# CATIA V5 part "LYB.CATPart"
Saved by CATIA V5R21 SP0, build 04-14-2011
Part number: LYB.SLDPRT
Bounding box of the stored display mesh (mm): x 1.55 to 5.05, y 3.678 to 6.478, z -1.805 to -0.004
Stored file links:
  C:\Users\user\Desktop\CATIA文件\0-最新文件(2025.3月之前的慎用)\LYB\LYB.CATPart
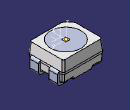
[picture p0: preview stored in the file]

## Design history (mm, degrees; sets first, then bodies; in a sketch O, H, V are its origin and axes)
AxisSystem1: origin (3.2993, 5.0728, -0.0046), X (0, -1, 0), Y (1, 0, 0), Z (0, 0, 1)
Set1
  DatumSurface1 to DatumSurface120
  Line1: stored without definition
  Circle1: stored without definition
  Line2: stored without definition
  Circle2: stored without definition
  Line3 to Line38: stored without definition
  Circle3: stored without definition
  Line39: stored without definition
  Circle4: stored without definition
  Line40 to Line43: stored without definition
  Circle5: stored without definition
  Circle6: stored without definition
  Line44 to Line46: stored without definition
  Circle7: stored without definition
  Line47: stored without definition
  Circle8: stored without definition
  Line48 to Line50: stored without definition
  Circle9 to Circle11: stored without definition
  Line51: stored without definition
  Circle12: stored without definition
  Line52: stored without definition
  Circle13 to Circle15: stored without definition
  Line53: stored without definition
  Circle16: stored without definition
  Line54: stored without definition
  Circle17 to Circle19: stored without definition
  Line55: stored without definition
  Circle20: stored without definition
  Line56: stored without definition
  Circle21 to Circle23: stored without definition
  Line57: stored without definition
  Circle24: stored without definition
  Line58: stored without definition
  Circle25: stored without definition
  Circle26: stored without definition
  Line59 to Line62: stored without definition
  Circle27: stored without definition
  Circle28: stored without definition
  Line63 to Line66: stored without definition
  Circle29: stored without definition
  Circle30: stored without definition
  Line67: stored without definition
  Circle31: stored without definition
  Line68: stored without definition
  Circle32: stored without definition
  Line69 to Line72: stored without definition
  Circle33: stored without definition
  Line73: stored without definition
  Circle34: stored without definition
  Circle35: stored without definition
  Line74: stored without definition
  Circle36: stored without definition
  Line75 to Line78: stored without definition
  Circle37: stored without definition
  Line79: stored without definition
  Circle38: stored without definition
  Line80 to Line82: stored without definition
  Circle39: stored without definition
  Line83: stored without definition
  Circle40: stored without definition
  Line84 to Line86: stored without definition
  Circle41: stored without definition
  Line87: stored without definition
  Circle42: stored without definition
  Line88 to Line90: stored without definition
  Circle43: stored without definition
  Line91: stored without definition
  Circle44: stored without definition
  Circle45: stored without definition
  Line92: stored without definition
  Circle46: stored without definition
  Line93 to Line95: stored without definition
  Circle47: stored without definition
  Line96: stored without definition
  Circle48: stored without definition
  Circle49: stored without definition
  Line97: stored without definition
  Circle50: stored without definition
  Line98 to Line100: stored without definition
  Circle51: stored without definition
  Line101: stored without definition
  Circle52: stored without definition
  Line102 to Line104: stored without definition
  Circle53: stored without definition
  Line105: stored without definition
  Circle54: stored without definition
  Line106 to Line108: stored without definition
  Circle55: stored without definition
  Line109: stored without definition
  Circle56: stored without definition
  Line110 to Line112: stored without definition
  Circle57: stored without definition
  Line113: stored without definition
  Circle58: stored without definition
  Line114: stored without definition
  Circle59: stored without definition
  Line115: stored without definition
  Circle60: stored without definition
  Line116 to Line118: stored without definition
  Circle61: stored without definition
  Line119: stored without definition
  Circle62: stored without definition
  Line120 to Line132: stored without definition
  Circle63: stored without definition
  Line133: stored without definition
  Circle64: stored without definition
  Line134 to Line136: stored without definition
  Circle65: stored without definition
  Line137: stored without definition
  Circle66: stored without definition
  Line138: stored without definition
  Circle67: stored without definition
  Line139: stored without definition
  Circle68: stored without definition
  Line140 to Line143: stored without definition
  Circle69: stored without definition
  Circle70: stored without definition
  Line144 to Line153: stored without definition
  Circle71: stored without definition
  Line154: stored without definition
  Circle72: stored without definition
  Line155 to Line157: stored without definition
  Circle73: stored without definition
  Line158: stored without definition
  Circle74: stored without definition
  Line159 to Line161: stored without definition
  Circle75: stored without definition
  Line162: stored without definition
  Circle76: stored without definition
  Line163 to Line165: stored without definition
  Circle77: stored without definition
  Line166: stored without definition
  Circle78: stored without definition
  Line167 to Line169: stored without definition
  Circle79: stored without definition
  Line170: stored without definition
  Circle80: stored without definition
  Line171 to Line173: stored without definition
  Circle81: stored without definition
  Line174: stored without definition
  Circle82: stored without definition
  Line175 to Line177: stored without definition
  Circle83: stored without definition
  Line178: stored without definition
  Circle84: stored without definition
  Line179 to Line181: stored without definition
  Circle85: stored without definition
  Line182: stored without definition
  Circle86: stored without definition
  Line183 to Line185: stored without definition
  Circle87: stored without definition
  Line186: stored without definition
  Circle88: stored without definition
  Line187 to Line189: stored without definition
  Circle89: stored without definition
  Line190: stored without definition
  Circle90: stored without definition
  Line191 to Line193: stored without definition
  Circle91: stored without definition
  Line194: stored without definition
  Circle92: stored without definition
  Line195 to Line197: stored without definition
  Circle93: stored without definition
  Line198: stored without definition
  Circle94: stored without definition
  Line199 to Line201: stored without definition
  Circle95: stored without definition
  Line202: stored without definition
  Circle96: stored without definition
  Line203 to Line205: stored without definition
  Circle97: stored without definition
  Line206: stored without definition
  Circle98: stored without definition
  Line207 to Line209: stored without definition
  Circle99: stored without definition
  Line210: stored without definition
  Circle100: stored without definition
  Line211 to Line213: stored without definition
  Circle101: stored without definition
  Line214: stored without definition
  Circle102: stored without definition
  Line215 to Line217: stored without definition
  Circle103: stored without definition
  Line218: stored without definition
  Circle104: stored without definition
  Line219 to Line221: stored without definition
  Circle105: stored without definition
  Line222: stored without definition
  Circle106: stored without definition
  Line223 to Line225: stored without definition
  Circle107: stored without definition
  Line226: stored without definition
  Circle108: stored without definition
  Line227 to Line229: stored without definition
  Circle109: stored without definition
  Line230: stored without definition
  Circle110: stored without definition
  Line231 to Line241: stored without definition
  DatumSurface121 to DatumSurface179
  Circle111: stored without definition
  Line242: stored without definition
  Circle112: stored without definition
  Line243: stored without definition
  Circle113 to Circle115: stored without definition
  Line244: stored without definition
  Circle116: stored without definition
  Line245 to Line248: stored without definition
  Circle117: stored without definition
  Circle118: stored without definition
  Line249 to Line251: stored without definition
  Circle119: stored without definition
  Line252: stored without definition
  Circle120: stored without definition
  Line253 to Line256: stored without definition
  Circle121: stored without definition
  Circle122: stored without definition
  Line257 to Line261: stored without definition
  Circle123: stored without definition
  Circle124: stored without definition
  Line262 to Line265: stored without definition
  Circle125 to Circle128: stored without definition
  Line266 to Line270: stored without definition
  Circle129: stored without definition
  Circle130: stored without definition
  Line271 to Line274: stored without definition
  Circle131: stored without definition
  Circle132: stored without definition
  Line275 to Line277: stored without definition
  Circle133: stored without definition
  Circle134: stored without definition
  Line278 to Line282: stored without definition
  Circle135: stored without definition
  Circle136: stored without definition
  Line283 to Line286: stored without definition
  Circle137: stored without definition
  Circle138: stored without definition
  Line287 to Line289: stored without definition
  Circle139: stored without definition
  Circle140: stored without definition
  Line290 to Line293: stored without definition
  Circle141: stored without definition
  Circle142: stored without definition
  Line294 to Line298: stored without definition
  Circle143: stored without definition
  Circle144: stored without definition
  Line299 to Line302: stored without definition
  Circle145: stored without definition
  Circle146: stored without definition
  Line303 to Line306: stored without definition
  Circle147: stored without definition
  Circle148: stored without definition
  Line307 to Line310: stored without definition
  Circle149: stored without definition
  Circle150: stored without definition
  Line311: stored without definition
  Circle151: stored without definition
  Line312: stored without definition
  Circle152 to Circle154: stored without definition
  Line313 to Line316: stored without definition
  Circle155: stored without definition
  Circle156: stored without definition
  Line317 to Line320: stored without definition
  Circle157: stored without definition
  Circle158: stored without definition
  Line321: stored without definition
  Line322: stored without definition
  Circle159: stored without definition
  Circle160: stored without definition
  Line323 to Line325: stored without definition
  Circle161: stored without definition
  Circle162: stored without definition
  Line326 to Line330: stored without definition
  Circle163: stored without definition
  Circle164: stored without definition
  Line331 to Line334: stored without definition
  Circle165: stored without definition
  Circle166: stored without definition
  Line335 to Line337: stored without definition
  Circle167: stored without definition
  Circle168: stored without definition
  Line338 to Line342: stored without definition
  Circle169: stored without definition
  Line343 to Line345: stored without definition
  Circle170: stored without definition
  Line346 to Line352: stored without definition
  DatumSurface180 to DatumSurface390
  Circle171: stored without definition
  Circle172: stored without definition
  Line353: stored without definition
  Line354: stored without definition
  Circle173: stored without definition
  Circle174: stored without definition
  DatumCurve1
  Line355: stored without definition
  Line356: stored without definition
  Circle175: stored without definition
  Line357: stored without definition
  DatumCurve2
  Circle176: stored without definition
  Line358: stored without definition
  Circle177 to Circle183: stored without definition
  Line359: stored without definition
  Line360: stored without definition
  Circle184 to Circle188: stored without definition
  Line361: stored without definition
  Circle189: stored without definition
  Line362: stored without definition
  Circle190 to Circle192: stored without definition
  Line363: stored without definition
  Circle193: stored without definition
  Line364: stored without definition
  Circle194 to Circle196: stored without definition
  Line365: stored without definition
  Circle197: stored without definition
  Line366: stored without definition
  Circle198 to Circle200: stored without definition
  Line367: stored without definition
  Circle201: stored without definition
  Line368: stored without definition
  Circle202 to Circle204: stored without definition
  Line369 to Line373: stored without definition
  Circle205: stored without definition
  Line374: stored without definition
  Circle206 to Circle208: stored without definition
  Line375: stored without definition
  Circle209: stored without definition
  Line376: stored without definition
  Circle210: stored without definition
  Line377 to Line379: stored without definition
  Circle211: stored without definition
  Circle212: stored without definition
  Line380 to Line383: stored without definition
  Circle213: stored without definition
  Circle214: stored without definition
  Line384 to Line388: stored without definition
  Circle215: stored without definition
  Circle216: stored without definition
  Line389 to Line391: stored without definition
  Circle217: stored without definition
  Circle218: stored without definition
  Line392: stored without definition
  Line393: stored without definition
  Circle219: stored without definition
  Circle220: stored without definition
  Line394 to Line397: stored without definition
  Circle221: stored without definition
  Circle222: stored without definition
  Line398 to Line401: stored without definition
  Circle223 to Circle226: stored without definition
  Line402 to Line405: stored without definition
  Circle227: stored without definition
  Circle228: stored without definition
  Line406 to Line409: stored without definition
  Circle229: stored without definition
  Circle230: stored without definition
  Line410 to Line413: stored without definition
  Circle231: stored without definition
  Circle232: stored without definition
  Line414 to Line417: stored without definition
  Circle233: stored without definition
  Circle234: stored without definition
  Line418 to Line422: stored without definition
  Circle235: stored without definition
  Circle236: stored without definition
  Line423 to Line426: stored without definition
  Circle237: stored without definition
  Circle238: stored without definition
  Line427 to Line429: stored without definition
  Circle239: stored without definition
  Circle240: stored without definition
  Line430 to Line433: stored without definition
  Circle241: stored without definition
  Circle242: stored without definition
  Line434 to Line438: stored without definition
  Circle243: stored without definition
  Circle244: stored without definition
  Line439 to Line441: stored without definition
  Circle245: stored without definition
  Circle246: stored without definition
  Line442 to Line445: stored without definition
  Circle247: stored without definition
  Circle248: stored without definition
  Line446 to Line450: stored without definition
  Circle249 to Circle252: stored without definition
  Line451 to Line454: stored without definition
  Circle253: stored without definition
  Circle254: stored without definition
  Line455 to Line459: stored without definition
  Circle255 to Circle257: stored without definition
  Line460: stored without definition
  Circle258: stored without definition
  Line461 to Line464: stored without definition
  Circle259: stored without definition
  Line465: stored without definition
  Circle260: stored without definition
  Line466 to Line468: stored without definition
  Circle261: stored without definition
  Line469: stored without definition
  Circle262: stored without definition
  Line470 to Line472: stored without definition
  Circle263: stored without definition
  Line473: stored without definition
  Circle264: stored without definition
  Line474 to Line476: stored without definition
  Circle265: stored without definition
  Line477: stored without definition
  Circle266: stored without definition
  Line478 to Line480: stored without definition
  Circle267: stored without definition
  Line481: stored without definition
  Circle268: stored without definition
  Line482 to Line484: stored without definition
  Circle269: stored without definition
  Line485: stored without definition
  Circle270: stored without definition
  Line486 to Line488: stored without definition
  Circle271: stored without definition
  Line489: stored without definition
  Circle272: stored without definition
  Line490 to Line492: stored without definition
  Circle273: stored without definition
  Line493: stored without definition
  Circle274: stored without definition
  Line494 to Line496: stored without definition
  Circle275: stored without definition
  Line497: stored without definition
  Circle276: stored without definition
  Line498 to Line500: stored without definition
  Circle277: stored without definition
  Line501: stored without definition
  Circle278: stored without definition
  Line502 to Line509: stored without definition
  Circle279: stored without definition
  Circle280: stored without definition
  DatumCurve3
  DatumCurve4
  Circle281: stored without definition
  Line510 to Line512: stored without definition
  DatumCurve5
  Circle282: stored without definition
  Circle283: stored without definition
  DatumCurve6
  DatumCurve7
  Line513: stored without definition
  DatumCurve8
  Line514: stored without definition
  Circle284: stored without definition
  DatumCurve9
  Circle285: stored without definition
  Line515: stored without definition
  Circle286: stored without definition
  Line516: stored without definition
  DatumCurve10
  Circle287: stored without definition
  Circle288: stored without definition
  Line517: stored without definition
  Line518: stored without definition
  DatumCurve11
  Circle289: stored without definition
  DatumCurve12
  Line519: stored without definition
  Circle290: stored without definition
  Line520: stored without definition
  DatumCurve13
  Circle291: stored without definition
  Line521: stored without definition
  Circle292: stored without definition
  Line522: stored without definition
  Line523: stored without definition
  Circle293: stored without definition
  Line524: stored without definition
  DatumCurve14
  Circle294: stored without definition
  Line525: stored without definition
  Line526: stored without definition
  Circle295: stored without definition
  Circle296: stored without definition
  Line527 to Line529: stored without definition
  DatumCurve15
  Line530: stored without definition
  Circle297: stored without definition
  DatumCurve16
  Line531: stored without definition
  Circle298: stored without definition
  Line532: stored without definition
  Line533: stored without definition
  DatumCurve17
  Circle299: stored without definition
  Line534: stored without definition
  Line535: stored without definition
  Circle300: stored without definition
  Circle301: stored without definition
  Line536: stored without definition
  Line537: stored without definition
  Circle302: stored without definition
  Line538: stored without definition
  Circle303: stored without definition
  Line539 to Line542: stored without definition
  DatumCurve18
  Line543: stored without definition
  DatumCurve19
  Circle304: stored without definition
  DatumCurve20
  Line544: stored without definition
  Circle305: stored without definition
  Line545: stored without definition
  DatumCurve21
  DatumCurve22
  Line546: stored without definition
  Circle306 to Circle308: stored without definition
  Line547: stored without definition
  Circle309: stored without definition
  Line548: stored without definition
  Line549: stored without definition
  DatumCurve23
  Line550 to Line555: stored without definition
  Circle310: stored without definition
  Line556: stored without definition
  Circle311: stored without definition
  Line557 to Line559: stored without definition
  Circle312: stored without definition
  Line560: stored without definition
  Circle313: stored without definition
  Line561 to Line580: stored without definition
  Circle314: stored without definition
  Line581: stored without definition
  DatumCurve24
  Line582: stored without definition
  DatumCurve25
  Line583 to Line588: stored without definition
  Circle315: stored without definition
  Line589: stored without definition
  Circle316: stored without definition
  Line590 to Line592: stored without definition
  Circle317: stored without definition
  Line593: stored without definition
  Circle318: stored without definition
  Line594 to Line596: stored without definition
  Circle319: stored without definition
  Line597: stored without definition
  Circle320: stored without definition
  Line598 to Line600: stored without definition
  Circle321: stored without definition
  Line601: stored without definition
  Circle322: stored without definition
  Line602 to Line604: stored without definition
  Circle323: stored without definition
  Line605: stored without definition
  Circle324: stored without definition
  Circle325: stored without definition
  Line606: stored without definition
  Circle326: stored without definition
  Line607 to Line609: stored without definition
  Circle327: stored without definition
  Line610: stored without definition
  Circle328: stored without definition
  Circle329: stored without definition
  Line611: stored without definition
  Circle330: stored without definition
  Line612 to Line614: stored without definition
  Circle331: stored without definition
  Line615: stored without definition
  Circle332: stored without definition
  Line616 to Line618: stored without definition
  Circle333: stored without definition
  Line619: stored without definition
  Circle334: stored without definition
  Line620 to Line622: stored without definition
  Circle335: stored without definition
  Line623: stored without definition
  Circle336: stored without definition
  Line624 to Line626: stored without definition
  Circle337: stored without definition
  Line627: stored without definition
  Circle338: stored without definition
  Line628 to Line634: stored without definition
  Circle339: stored without definition
  DatumCurve26
  Line635: stored without definition
  DatumCurve27
  Line636: stored without definition
  Line637: stored without definition
  DatumCurve28
  Line638: stored without definition
  DatumCurve29
  Circle340: stored without definition
  Line639: stored without definition
  DatumCurve30
  Line640 to Line642: stored without definition
  DatumCurve31
  Line643 to Line645: stored without definition
  DatumCurve32
  Circle341: stored without definition
  Line646 to Line650: stored without definition
  DatumCurve33
  Circle342: stored without definition
  Line651 to Line664: stored without definition
  Circle343: stored without definition
  Line665: stored without definition
  Circle344: stored without definition
  Line666: stored without definition
  Circle345: stored without definition
  Line667: stored without definition
  Circle346: stored without definition
  Line668: stored without definition
  Circle347: stored without definition
  Line669: stored without definition
  Circle348: stored without definition
  Line670: stored without definition
  Circle349: stored without definition
  DatumCurve34
  Line671 to Line674: stored without definition
  Circle350: stored without definition
  Line675 to Line677: stored without definition
  Circle351: stored without definition
  Line678: stored without definition
  Line679: stored without definition
  Circle352: stored without definition
  Line680 to Line683: stored without definition
  Circle353: stored without definition
  Line684: stored without definition
  Line685: stored without definition
  Circle354: stored without definition
  Line686 to Line688: stored without definition
  Circle355: stored without definition
  Line689 to Line692: stored without definition
  Circle356: stored without definition
  Line693 to Line702: stored without definition
  DatumCurve35
  Line703: stored without definition
  DatumCurve36
  Circle357: stored without definition
  Line704: stored without definition
  Line705: stored without definition
  Circle358: stored without definition
  Line706 to Line713: stored without definition
  Point1 "发光中心&几何中心（测试原点）": type Between, FirstPoint vertex [face of DatumSurface390], SecondPoint vertex [face of DatumSurface390], Ratio 0.5
  Point2 "虚拟坐标": (0.0154, 0.0149, -0.1409), relative to Point1, in AxisSystem1
Body1 (main body)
